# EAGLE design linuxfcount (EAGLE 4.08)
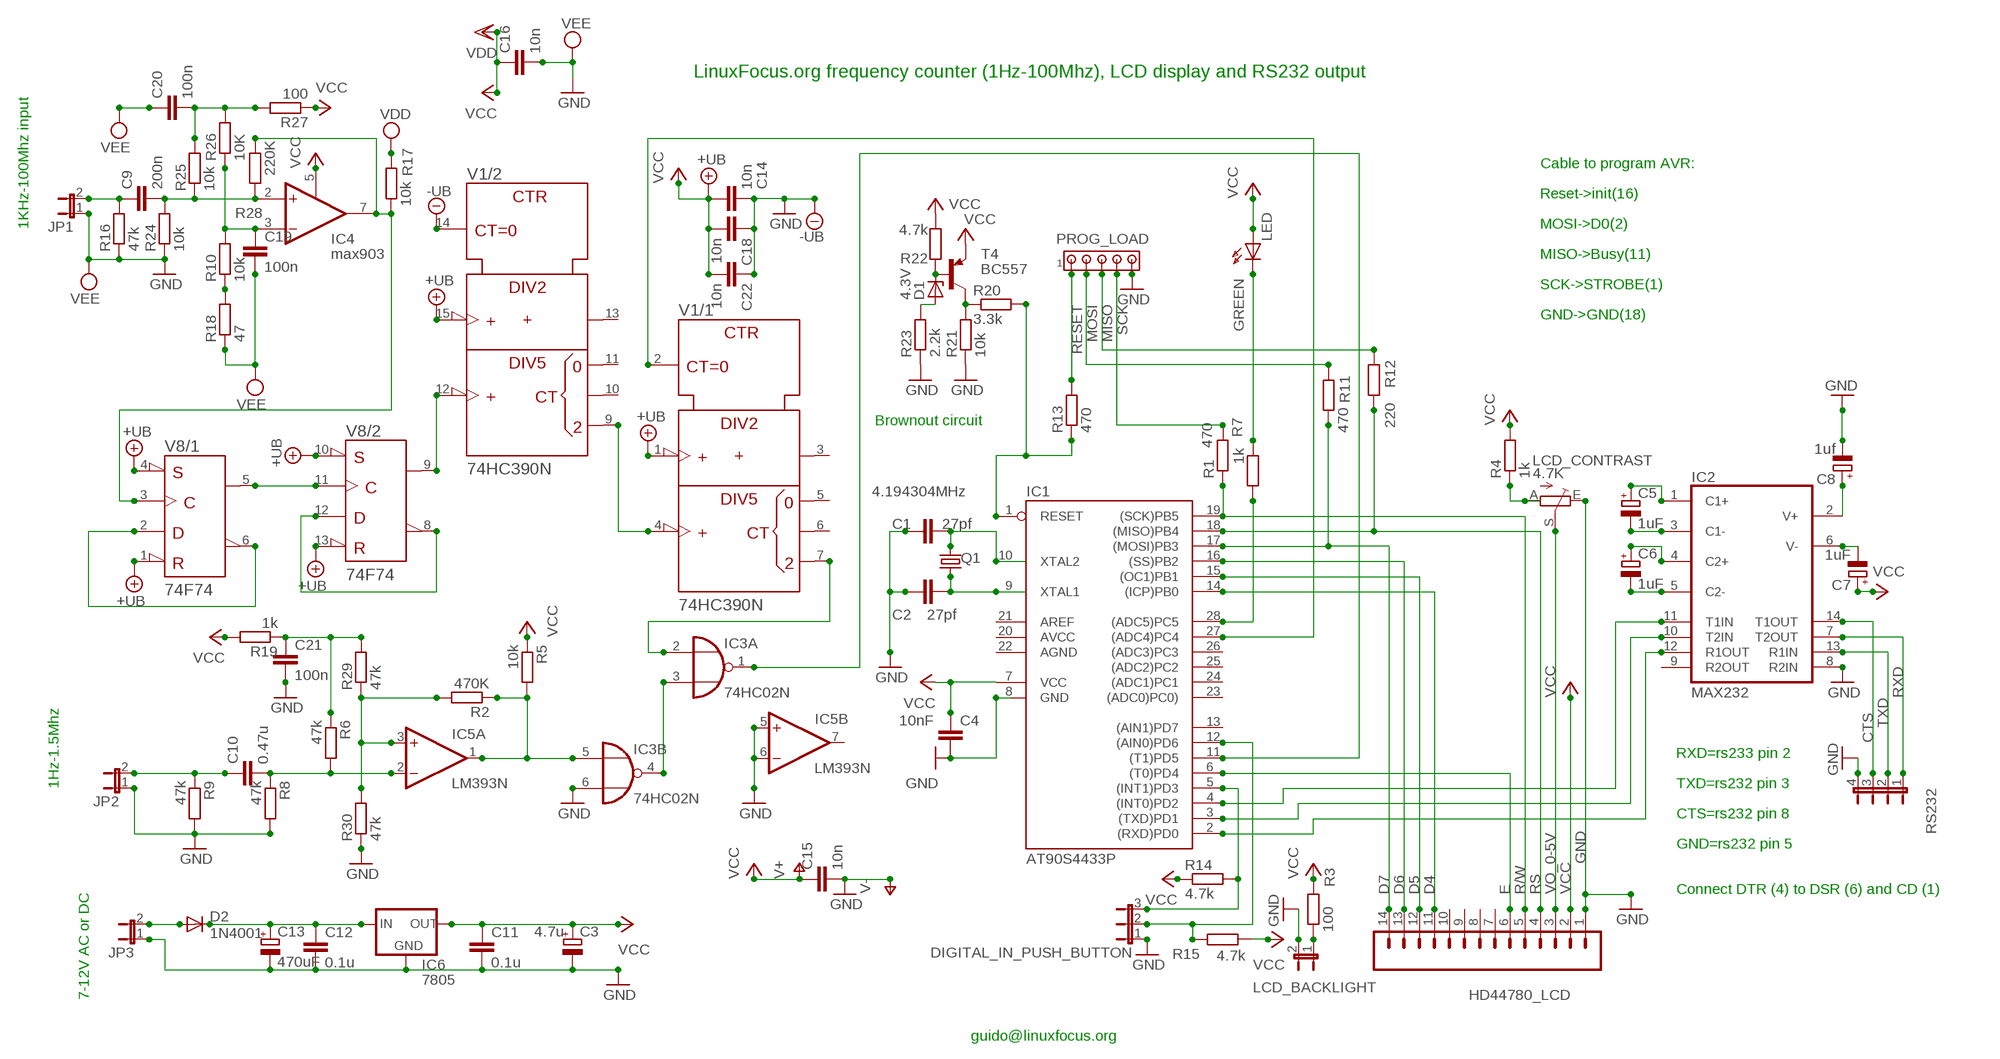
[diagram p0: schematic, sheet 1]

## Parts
C1  27pf  C2.5/2  [C2.5-2]
C2  27pf  C2.5/2  [C2.5-2]
C3  4.7u  CPOL-EUE2.5-7  [E2,5-7]
C4  10nF  C-EU025-030X050  [C025-030X050]
C5  1uF  CPOL-EUE2.5-6  [E2,5-6]
C6  1uF  CPOL-EUE2.5-6  [E2,5-6]
C7  1uF  CPOL-EUE2.5-6  [E2,5-6]
C8  1uf  CPOL-EUE2.5-6  [E2,5-6]
C9  200n  C-EU025-040X050  [C025-040X050]
C10  0.47u  C-EU025-040X050  [C025-040X050]
C11  0.1u  C-EU025-050X050  [C025-050X050]
C12  0.1u  C-EU025-050X050  [C025-050X050]
C13  470uF  CPOL-EUE5-10.5  [E5-10,5]
C14  10n  C-EU025-040X050  [C025-040X050]
C15  10n  C-EU025-040X050  [C025-040X050]
C16  10n  C-EU025-040X050  [C025-040X050]
C18  10n  C-EU025-040X050  [C025-040X050]
C19  100n  C-EU025-030X050  [C025-030X050]
C20  100n  C-EU025-030X050  [C025-030X050]
C21  100n  C-EU025-040X050  [C025-040X050]
C22  10n  C-EU025-030X050  [C025-030X050]
D1  4.3V  ZENER-DIODEZD-5  [ZDIO-5]
D2  1N4001  DIODE-DO07  [DO07]
DIGITAL_IN_PUSH_BUTTON  JP2E  [JP2]
GREEN  LED  LED3MM  [LED3MM]
HD44780_LCD  M14  [14P]
IC1  AT90S4433P  [DIL28-3]
IC2  MAX232  [DIL16]
IC3  74HC02N  [DIL14]
IC4  max903  MAX903CPA  [DIL08]
IC5  LM393N  [DIL08]
IC6  7805  78XXS  [78XXS]
JP1  JP1E  [JP1]
JP2  JP1E  [JP1]
JP3  JP1E  [JP1]
LCD_BACKLIGHT  JP1E  [JP1]
LCD_CONTRAST  4.7K  TRIM_EU-LI10  [LI10]
PROG_LOAD  MTA05-100  [10X05MTA]
Q1  4.194304MHz  HC49U-V  [HC49U-V]
R1  470  R-EU_0207/10  [0207/10]
R2  470K  R-EU_0204/5  [0204/5]
R3  100  R-EU_0204/5  [0204/5]
R4  1k  R-EU_0204/7  [0204/7]
R5  10k  R-EU_0204/7  [0204/7]
R6  47k  R-EU_0204/7  [0204/7]
R7  1k  R-EU_0204/7  [0204/7]
R8  47k  R-EU_0204/7  [0204/7]
R9  47k  R-EU_0204/7  [0204/7]
R10  10k  R-EU_0204/7  [0204/7]
R11  470  R-EU_0207/10  [0207/10]
R12  220  R-EU_0207/10  [0207/10]
R13  470  R-EU_0204/5  [0204/5]
R14  4.7k  R-EU_0207/10  [0207/10]
R15  4.7k  R-EU_0204/7  [0204/7]
R16  47k  R-EU_0204/7  [0204/7]
R17  10k  R-EU_0204/7  [0204/7]
R18  47  R-EU_0204/7  [0204/7]
R19  1k  R-EU_0204/7  [0204/7]
R20  3.3k  R-EU_0204/7  [0204/7]
R21  10k  R-EU_0204/7  [0204/7]
R22  4.7k  R-EU_0204/7  [0204/7]
R23  2.2k  R-EU_0204/7  [0204/7]
R24  10k  R-EU_0204/7  [0204/7]
R25  10k  R-EU_0204/5  [0204/5]
R26  10K  R-EU_0204/5  [0204/5]
R27  100  R-EU_0204/7  [0204/7]
R28  220K  R-EU_0204/5  [0204/5]
R29  47k  R-EU_0204/7  [0204/7]
R30  47k  R-EU_0204/5  [0204/5]
RS232  JP4E  [JP4]
T4  BC557  [TO92]
V1  74HC390N  74390N  [DIL16]
V8  74F74  7474N  [DIL14]

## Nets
+UB: V1.1(/1:CKA) V1.15(/2:CKA) V8.1(/1:CLR\) V8.4(/1:PRE\) V8.10(/2:PRE\) V8.13(/2:CLR\)
-UB: V1.14(/2:CLR)
CTS: IC2.14(T1OUT) RS232.3
D4: HD44780_LCD.11 IC1.14((ICP)PB0)
D5: HD44780_LCD.12 IC1.15((OC1)PB1)
D6: HD44780_LCD.13 IC1.16((SS)PB2)
D7: HD44780_LCD.14 IC1.17((MOSI)PB3) R11.1
E: HD44780_LCD.6 IC1.6((T0)PD4)
GND: C1.1 C2.1 C3.- C4.2 C8.- C11.2 C12.2 C13.- C14.2 C18.1 C21.2 C22.1 DIGITAL_IN_PUSH_BUTTON.1 HD44780_LCD.1 IC1.8(GND) IC2.8(R2IN) IC3.6(B:I1) IC5.5(B:+IN) IC5.6(B:-IN) IC6.GND JP1.1 JP2.1 JP3.1 LCD_BACKLIGHT.2 LCD_CONTRAST.E PROG_LOAD.5 R8.2 R9.2 R16.1 R21.1 R23.1 R24.1 R30.1 RS232.4 ; supply symbol labelled -UB, VEE
MISO: PROG_LOAD.3 R12.2
MOSI: PROG_LOAD.2 R11.2
N$1: IC3.3(A:I1) IC3.4(B:O)
N$2: C2.2 IC1.9(XTAL1) Q1.1
N$3: LCD_BACKLIGHT.1 R3.1
N$4: IC3.2(A:I0) V1.7(/1:QD)
N$5: IC1.28((ADC5)PC5) R7.2
N$6: DIGITAL_IN_PUSH_BUTTON.3 IC1.5((INT1)PD3) R14.2
N$7: GREEN.K(C) R7.1
N$8: V1.4(/1:CKB) V1.9(/2:QD)
N$9: V1.12(/2:CKB) V8.9(/2:Q)
N$10: C9.2 IC4.2(+IN) R24.2 R25.1 R28.1
N$11: C20.2 R25.2 R26.2 R27.2
N$12: V8.8(/2:Q\) V8.12(/2:D)
N$14: V8.5(/1:Q) V8.11(/2:CLK)
N$15: C19.1 IC4.3(-IN) R10.2 R26.1
N$16: R10.1 R18.2
N$17: C9.1 JP1.2 R16.2
N$18: C10.2 IC5.2(A:-IN) R6.2 R8.1
N$19: DIGITAL_IN_PUSH_BUTTON.2 IC1.12((AIN0)PD6) R15.2
N$20: C21.1 R6.1 R19.1 R29.2
N$21: IC5.3(A:+IN) R2.2 R29.1 R30.2
N$24: IC1.1(RESET) R13.1 R20.2
N$25: C6.- IC2.5(C2-)
N$26: C6.+ IC2.4(C2+)
N$27: C7.- IC2.6(V-)
N$28: C8.+ IC2.2(V+)
N$29: C5.- IC2.3(C1-)
N$30: C5.+ IC2.1(C1+)
N$31: IC1.3((TXD)PD1) IC2.10(T2IN)
N$32: IC1.4((INT0)PD2) IC2.11(T1IN)
N$34: IC1.2((RXD)PD0) IC2.12(R1OUT)
N$36: C1.2 IC1.10(XTAL2) Q1.2
N$37: IC4.7(OUT) R17.1 R28.2 V8.3(/1:CLK)
N$39: IC3.5(B:I0) IC5.1(A:OUT) R2.1 R5.2
N$40: IC1.11((T1)PD5) IC3.1(A:O)
N$42: C10.1 JP2.2 R9.1
N$45: LCD_CONTRAST.A R4.1
N$46: R20.1 R21.2 T4.3(C)
N$47: D1.A R23.2
N$48: D1.C R22.1 T4.2(B)
N$49: D2.A JP3.2
N$50: IC1.27((ADC4)PC4) V1.2(/1:CLR)
N$51: C12.1 C13.+ D2.C IC6.IN
N$52: V8.2(/1:D) V8.6(/1:Q\)
R/W: HD44780_LCD.5 IC1.19((SCK)PB5) R1.1
RESET: PROG_LOAD.1 R13.2
RS: HD44780_LCD.4 IC1.18((MISO)PB4) R12.1
RXD: IC2.7(T2OUT) RS232.1
SCK: PROG_LOAD.4 R1.2
TXD: IC2.13(R1IN) RS232.2
V+: C15.1 ; supply symbol labelled VCC
V-: C15.2 ; supply symbol labelled GND
VCC: C3.+ C4.1 C7.+ C11.1 C14.1 C16.1 C18.2 C22.2 GREEN.A HD44780_LCD.2 IC1.7(VCC) IC4.5(LATCH) IC6.OUT R3.2 R4.2 R5.1 R14.1 R15.1 R17.2 R19.2 R22.2 R27.1 T4.1(E) ; supply symbol labelled +UB, VDD
VEE: C16.2 C19.2 C20.1 R18.1 ; supply symbol labelled GND
VO_0-5V: HD44780_LCD.3 LCD_CONTRAST.S
Unconnected: HD44780_LCD.7 HD44780_LCD.8 HD44780_LCD.9 HD44780_LCD.10 IC1.13((AIN1)PD7) IC1.23((ADC0)PC0)) IC1.24((ADC1)PC1) IC1.25((ADC2)PC2) IC1.26((ADC3)PC3) IC2.9(R2OUT) IC3.8(C:I0) IC3.9(C:I1) IC3.10(C:O) IC3.11(D:I0) IC3.12(D:I1) IC3.13(D:O) IC5.7(B:OUT) V1.3(/1:QA) V1.5(/1:QB) V1.6(/1:QC) V1.10(/2:QC) V1.11(/2:QB) V1.13(/2:QA)

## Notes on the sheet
- LinuxFocus.org frequency counter (1Hz-100Mhz), LCD display and RS232 output
- Cable to program AVR:
- Reset->init(16)
- 1KHz-100Mhz input | MOSI->D0(2)
- MISO->Busy(11)
- SCK->STROBE(1)
- GND->GND(18)
- Brownout circuit
- RXD=rs233 pin 2
- 1Hz-1.5Mhz | TXD=rs232 pin 3
- CTS=rs232 pin 8
- GND=rs232 pin 5
- Connect DTR (4) to DSR (6) and CD (1)
- 7-12V AC or DC
- guido@linuxfocus.org

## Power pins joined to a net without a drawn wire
AGND: IC1.22(AGND)
AREF: IC1.21(AREF)
AVCC: IC1.20(AVCC)
GND: IC2.15(GND) IC3.7(P:GND) IC4.4(VEE) IC4.6(GND) V1.8(/-UB:-UB) V8.7(/-UB:-UB)
V+: IC5.8(P:V+)
V-: IC5.4(P:V-)
VCC: IC2.16(VCC) IC3.14(P:VCC) IC4.1(VCC) IC4.8(VDD) V1.16(/+UB:+UB) V8.14(/+UB:+UB)

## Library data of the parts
C1 C2 = capacitor-wima:C: CAPACITOR
C3 C5-C8 = rcl:CPOL-EU: POLARIZED CAPACITOR, European symbol
C4 = rcl:C-EU: CAPACITOR, European symbol
C9-C12 C14-C16 C18-C22 = rclgus:C-EU: CAPACITOR, European symbol
C13 = rclgus:CPOL-EU: POLARIZED CAPACITOR, European symbol
D1 = diode:ZENER-DIODE: Z-Diode
D2 = diode:DIODE-: DIODE
DIGITAL_IN_PUSH_BUTTON = jumper:JP2E: JUMPER
GREEN = led:LED3MM: LED
HD44780_LCD = con-amp-quick:M14: AMP QUICK CONNECTOR
IC1 = atmel:AT90S4433: MICROCONTROLLER 4 Kbytes FLASH 128 bytes SRAM 256 bytes EEPROM UART 6-channel 10 bit ADC
IC2 = maxim:MAX232: RS232 TRANSEIVER
IC3 = 74xx-eu:74*02: Quad 2-input NOR gate
IC4 = maxim2:MAX903CPA: VOLTAGE COMPARATOR
IC5 = linear:LM393: COMPARATOR
IC6 = v-reg:78XXS: VOLTAGE REGULATOR
JP1-JP3 LCD_BACKLIGHT = jumper:JP1E: JUMPER
LCD_CONTRAST = pot:TRIM_EU-: POTENTIOMETER
PROG_LOAD = con-amp:MTA05-100: AMP CONNECTOR
Q1 = crystal:HC49U-V: CRYSTAL
R1 R3 R7 R11-R14 R28 = rcl:R-EU_: RESISTOR, European symbol
R2 R5 R6 R8-R10 R16-R19 R24-R27 R29 R30 = rclgus:R-EU_: RESISTOR, European symbol
R4 R15 R20-R23 = rcl_gus:R-EU_: RESISTOR, European symbol
RS232 = jumper:JP4E: JUMPER
T4 = transistor-pnp:BC557: PNP TRANSISTOR
V1 = 74ttl-din:74*390: Dual 4-bit decade and binary COUNTER
V8 = 74ttl-din:74*74: Dual D type positive edge triggered FLIP FLOP, preset and clear

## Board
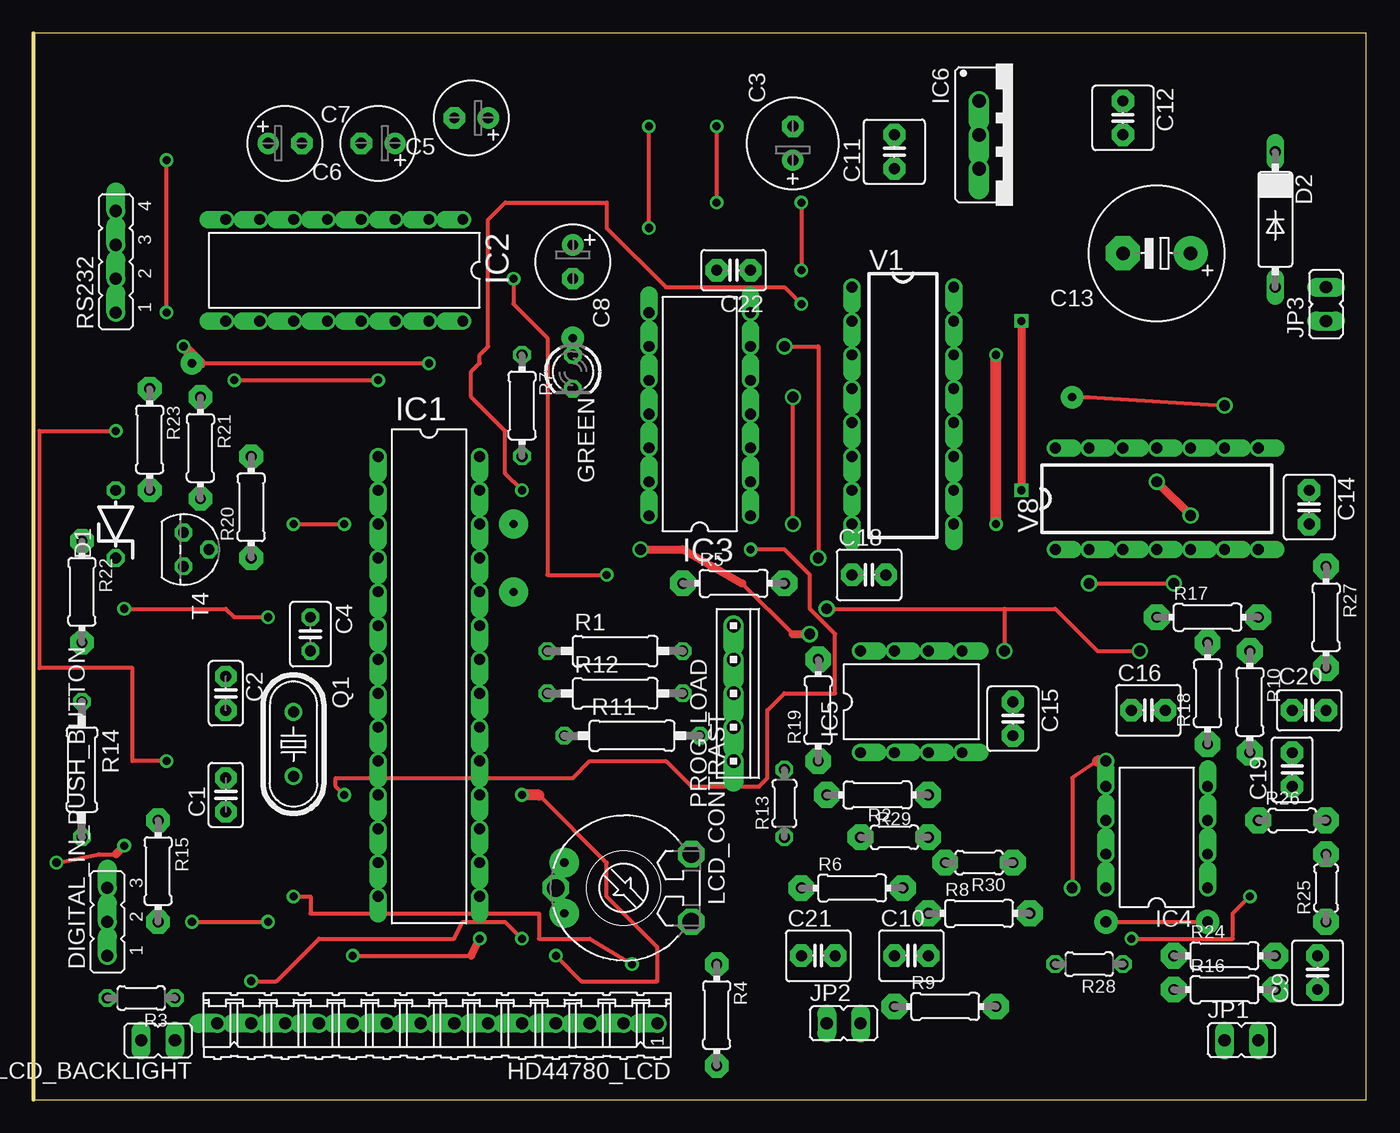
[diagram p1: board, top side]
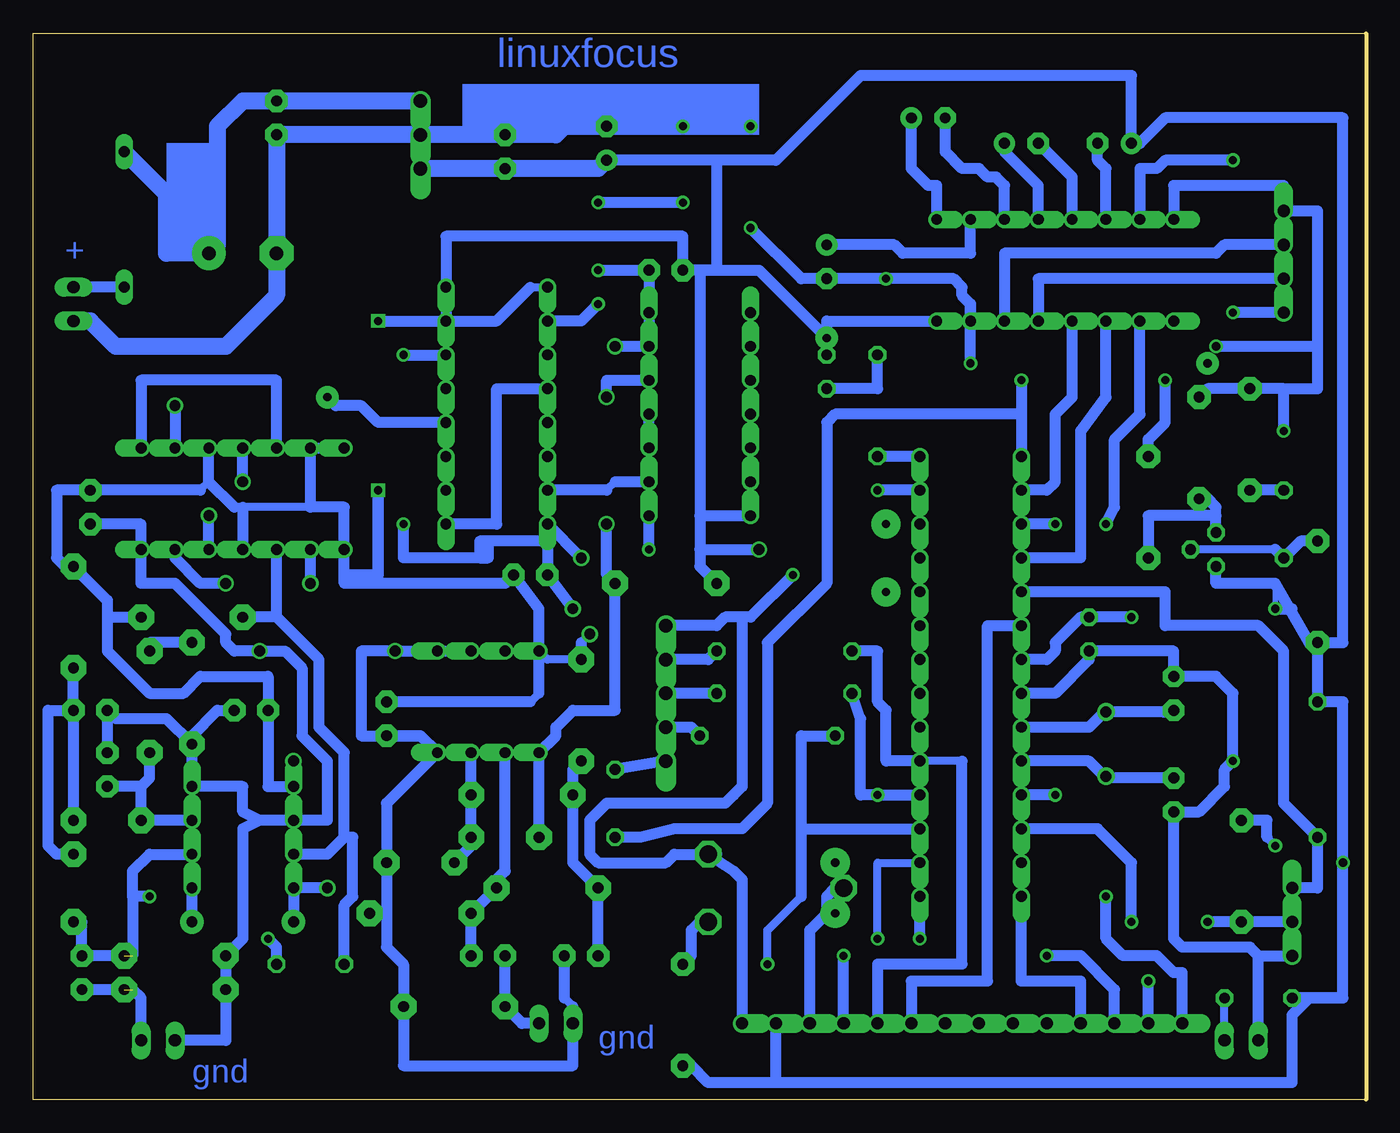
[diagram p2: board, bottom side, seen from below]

Size 100 x 80 mm. Coordinates in mm from the lower left corner, seen from the top.
Outline: 0,0 100,0 100,80 0,80 0,0
Copper layers used: Top, Bottom

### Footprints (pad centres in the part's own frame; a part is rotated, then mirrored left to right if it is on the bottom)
C2.5-2 = drill 0.813 pad 1.6 octagon: 1 -1.27,0; 2 1.27,0
E2,5-7 = drill 0.813 pad 1.6 round: + -1.27,0 | drill 0.813 pad 1.6 octagon: - 1.27,0
C025-030X050 = drill 0.813 octagon: 1 -1.27,0; 2 1.27,0
E2,5-6 = drill 0.813 pad 1.6 round: + -1.27,0 | drill 0.813 pad 1.6 octagon: - 1.27,0
C025-040X050 = drill 0.813 pad 1.676 octagon: 1 -1.27,0; 2 1.27,0
C025-050X050 = drill 0.813 pad 1.676 octagon: 1 -1.27,0; 2 1.27,0
E5-10,5 = drill 1.016 pad 2.54 round: + -2.54,0 | drill 1.016 pad 2.54 octagon: - 2.54,0
C025-030X050' = drill 0.813 pad 1.676 octagon: 1 -1.27,0; 2 1.27,0
ZDIO-5 = drill 0.813 octagon: A 2.54,0; C -2.54,0
DO07 = drill 0.813 long: A 5.08,0; C -5.08,0
JP2 = drill 0.914 offset: 1 -2.54,0; 2 0,0; 3 2.54,0
LED3MM = drill 0.813 octagon: A -1.27,0; K 1.27,0
14P = drill 0.914 offset: 1 -16.51,0; 2 -13.97,0; 3 -11.43,0; 4 -8.89,0; 5 -6.35,0; 6 -3.81,0; 7 -1.27,0; 8 1.27,0; 9 3.81,0; 10 6.35,0; 11 8.89,0; 12 11.43,0; 13 13.97,0; 14 16.51,0
DIL28-3 = drill 0.813 offset: 1 -16.51,-3.81; 2 -13.97,-3.81; 3 -11.43,-3.81; 4 -8.89,-3.81; 5 -6.35,-3.81; 6 -3.81,-3.81; 7 -1.27,-3.81; 8 1.27,-3.81; 9 3.81,-3.81; 10 6.35,-3.81; 11 8.89,-3.81; 12 11.43,-3.81; 13 13.97,-3.81; 14 16.51,-3.81; 15 16.51,3.81; 16 13.97,3.81; 17 11.43,3.81; 18 8.89,3.81; 19 6.35,3.81; 20 3.81,3.81; 21 1.27,3.81; 22 -1.27,3.81; 23 -3.81,3.81; 24 -6.35,3.81; 25 -8.89,3.81; 26 -11.43,3.81; 27 -13.97,3.81; 28 -16.51,3.81
DIL16 = drill 0.813 offset: 1 -8.89,-3.81; 2 -6.35,-3.81; 3 -3.81,-3.81; 4 -1.27,-3.81; 5 1.27,-3.81; 6 3.81,-3.81; 7 6.35,-3.81; 8 8.89,-3.81; 9 8.89,3.81; 10 6.35,3.81; 11 3.81,3.81; 12 1.27,3.81; 13 -1.27,3.81; 14 -3.81,3.81; 15 -6.35,3.81; 16 -8.89,3.81
DIL14 = drill 0.8 offset: 1 -7.62,-3.81; 2 -5.08,-3.81; 3 -2.54,-3.81; 4 0,-3.81; 5 2.54,-3.81; 6 5.08,-3.81; 7 7.62,-3.81; 8 7.62,3.81; 9 5.08,3.81; 10 2.54,3.81; 11 0,3.81; 12 -2.54,3.81; 13 -5.08,3.81; 14 -7.62,3.81
DIL08 = drill 0.813 offset: 1 -3.81,-3.81; 2 -1.27,-3.81; 3 1.27,-3.81; 4 3.81,-3.81; 5 3.81,3.81; 6 1.27,3.81; 7 -1.27,3.81; 8 -3.81,3.81
78XXS = drill 1.016 offset: GND 0,-2.54; IN -2.54,-2.54; OUT 2.54,-2.54
JP1 = drill 0.914 long: 1 0,-1.27; 2 0,1.27
LI10 = drill 1.321 octagon: A -2.54,-5.08; E 2.54,-5.08; S 0,5.08
10X05MTA = drill 1.016 offset: 1 5.08,0; 2 2.54,0; 3 0,0; 4 -2.54,0; 5 -5.08,0
HC49U-V = drill 0.813 round: 1 -2.413,0; 2 2.413,0
0207/10 = drill 0.813 octagon: 1 -5.08,0; 2 5.08,0
0204/5 = drill 0.813 pad 1.93 octagon: 1 -2.54,0; 2 2.54,0
0204/5' = drill 0.813 octagon: 1 -2.54,0; 2 2.54,0
0204/7 = drill 0.813 pad 1.778 octagon: 1 -3.81,0; 2 3.81,0
0204/7' = drill 0.813 pad 1.93 octagon: 1 -3.81,0; 2 3.81,0
0204/7'' = drill 0.813 octagon: 1 -3.81,0; 2 3.81,0
JP4 = drill 0.914 offset: 1 -3.81,0; 2 -1.27,0; 3 1.27,0; 4 3.81,0
TO92 = drill 0.813 octagon: 1 1.27,0; 2 0,1.905; 3 -1.27,0
DIL14' = drill 0.813 offset: 1 -7.62,-3.81; 2 -5.08,-3.81; 3 -2.54,-3.81; 4 0,-3.81; 5 2.54,-3.81; 6 5.08,-3.81; 7 7.62,-3.81; 8 7.62,3.81; 9 5.08,3.81; 10 2.54,3.81; 11 0,3.81; 12 -2.54,3.81; 13 -5.08,3.81; 14 -7.62,3.81

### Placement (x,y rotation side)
C1  14.44,22.86 90 top
C2  14.44,30.47 270 top
C3  56.98,71.75 90 top
C4  20.79,34.92 270 top
C5  32.85,73.66 180 top
C6  25.87,71.75 180 top
C7  18.88,71.75 0 top
C8  40.48,62.86 270 top
C9  96.36,9.52 90 top
C10  65.88,10.79 0 top
C11  64.61,71.11 90 top
C12  81.75,73.66 270 top
C13  84.29,63.5 180 top
C14  95.72,44.45 270 top
C15  73.5,28.57 270 top
C16  83.66,29.2 0 top
C18  62.7,39.37 0 top
C19  100n  [C025-030X050']  94.45,24.76 90 top
C20  100n  [C025-030X050']  95.72,29.2 0 top
C21  58.89,10.79 0 top
C22  10n  [C025-030X050']  52.54,62.23 180 top
D1  6.18,43.18 90 top
D2  93.18,66.03 270 top
DIGITAL_IN_PUSH_BUTTON  5.55,13.33 90 top
GREEN  40.48,54.61 270 top
HD44780_LCD  30.31,5.71 180 top
IC1  29.68,31.74 270 top
IC2  23.33,62.23 180 top
IC3  50,51.43 90 top
IC4  84.29,19.68 90 top
IC5  65.88,29.84 0 top
IC6  73.5,72.38 270 top
JP1  90.64,4.44 270 top
JP2  60.8,5.71 270 top
JP3  96.99,59.69 0 top
LCD_BACKLIGHT  9.36,4.44 90 top
LCD_CONTRAST  44.28,15.87 90 top
PROG_LOAD  52.54,30.47 270 top
Q1  19.52,26.66 270 top
R1  43.65,33.65 0 top
R2  64.61,19.68 0 top
R3  100  [0204/5']  8.09,7.62 180 top
R4  51.27,6.34 270 top
R5  10k  [0204/7']  52.54,38.73 0 top
R6  47k  [0204/7']  61.43,15.87 0 top
R7  1k  [0204/7'']  36.66,52.07 270 top
R8  47k  [0204/7']  70.95,13.97 0 top
R9  47k  [0204/7']  68.41,6.98 0 top
R10  10k  [0204/7']  91.28,29.84 270 top
R11  44.92,27.3 0 top
R12  43.65,30.47 0 top
R13  470  [0204/5']  56.35,22.22 90 top
R14  3.64,24.76 270 top
R15  9.36,17.14 270 top
R16  47k  [0204/7']  89.37,8.25 0 top
R17  10k  [0204/7']  88.1,36.19 0 top
R18  47  [0204/7']  88.1,30.47 90 top
R19  1k  [0204/7']  58.89,29.2 90 top
R20  16.34,44.45 90 top
R21  12.54,48.89 270 top
R22  3.64,38.1 270 top
R23  8.73,49.53 270 top
R24  10k  [0204/7']  89.37,10.79 0 top
R25  96.99,15.87 90 top
R26  94.45,20.95 0 top
R27  100  [0204/7']  96.99,36.19 270 top
R28  220K  [0204/5']  79.21,10.16 180 top
R29  47k  [0204/7']  63.34,22.86 180 top
R30  70.95,17.77 180 top
RS232  6.18,62.86 90 top
T4  11.27,41.27 270 top
V1  65.24,52.07 270 top
V8  74F74  [DIL14']  84.29,45.08 0 top

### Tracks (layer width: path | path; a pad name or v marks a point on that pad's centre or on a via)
+UB  (via drill 0.61)
  Top 0.305: v74.13,45.72 v74.13,58.41
  Bottom 0.61: 79.21,44.45 84.29,44.45 84.92,44.45 | 62.7,60.96 V1.1
  Bottom 0.813: 84.29,44.45 V8.4 | 84.92,44.45 86.83,46.35 V8.10 | 62.7,60.96 65.24,58.41 V1.15 v74.13,58.41 | 64.61,38.73 74.13,38.73 | 74.13,38.73 76.67,38.73 V8.1 76.67,44.45 79.21,44.45 V8.13 76.67,48.89 | 74.13,38.73 v74.13,45.72
CTS
  Bottom 0.813: IC2.14 27.14,63.5 11.27,63.5 10.63,64.13 RS232.3
D4
  Bottom 0.813: IC1.14 25.87,8.89 21.42,8.89 HD44780_LCD.11
D5  (via drill 0.61)
  Top 0.305: v23.96,10.79 32.85,10.79
  Top 0.61: 32.85,10.79 v33.49,12.06
  Bottom 0.813: HD44780_LCD.12 18.88,8.25 21.42,10.79 v23.96,10.79 | v33.49,12.06 IC1.15
D6  (via drill 0.61)
  Top 0.305: v16.34,8.89 18.25,8.89 21.42,12.06 31.58,12.06 32.22,13.33 35.39,13.33 v36.66,12.06
  Bottom 0.61: v36.66,12.06 36.66,17.77 IC1.16
  Bottom 0.813: HD44780_LCD.13 v16.34,8.89
D7  (via drill 0.61)
  Top 0.305: v19.52,15.24 20.79,15.24 20.79,13.97 37.94,13.97 37.94,12.06 41.74,12.06 v44.92,10.16
  Bottom 0.61: v44.92,10.16 44.92,12.7 42.38,15.24
  Bottom 0.813: R11.1 42.38,27.3 42.38,20.31 | 42.38,15.24 42.38,20.31 | HD44780_LCD.14 13.81,9.52 14.44,9.52 15.71,10.79 18.25,10.79 19.52,12.06 v19.52,15.24 | 42.38,20.31 IC1.17
E
  Bottom 0.813: HD44780_LCD.6 34.12,8.89 28.41,8.89 28.41,35.55 IC1.6
GND  (via drill 0.61, 0.81)
  Top 0.305: v83.02,33.65 79.84,33.65 76.67,36.83 72.86,36.83 | v59.52,36.83 72.86,36.83 | 72.86,36.83 v72.86,33.65 | v56.35,56.51 58.89,56.51 v58.89,40.64 | v72.22,43.18 v72.22,55.88 | v46.19,65.4 v46.19,73.02 | v57.62,67.3 v57.62,62.23 | v51.27,73.02 v51.27,67.3 | 12.54,55.24 v29.68,55.24 | v6.18,50.16 0.47,50.16 0.47,32.38 7.46,32.38 7.46,25.39 v10,25.39 | v43.02,39.37 38.57,39.37 38.57,57.15 36.03,59.69 v36.03,61.59
  Top 0.813: v72.22,43.18 v72.22,55.88 | v11.27,56.51 12.54,55.24
  Bottom 0.61: 59.52,6.98 60.16,7.62 | V1.8 61.43,41.91
  Bottom 0.813: IC4.4 84.29,23.49 84.29,21.58 83.02,20.95 | 83.02,20.95 IC4.6 77.94,20.95 77.94,25.39 79.84,27.3 79.84,32.38 81.11,33.65 v83.02,33.65 84.92,33.65 85.56,34.29 85.56,34.92 89.37,38.73 91.91,38.73 V8.7 91.91,43.18 C14.2 | 83.02,20.95 84.29,20.31 84.29,12.06 R24.1 R16.1 85.56,4.44 JP1.1 | 73.5,13.97 73.5,11.43 72.22,10.16 R9.2 72.22,2.54 59.52,2.54 JP2.1 59.52,6.98 | 73.5,13.97 R30.1 73.5,22.22 69.69,26.03 70.95,27.3 75.4,27.3 75.4,33.65 v72.86,33.65 IC5.5 IC5.6 | 73.5,13.97 R8.2 | 60.16,7.62 C21.2 | v59.52,36.83 C18.1 61.43,41.91 | v56.35,56.51 IC3.6 IC3.7 C22.1 v57.62,62.23 | v58.89,40.64 V1.8 | IC1.8 23.33,30.47 20.79,33.02 C4.2 14.44,33.65 C2.1 11.27,31.74 10,30.47 v10,25.39 10.63,24.76 10.63,23.49 12.54,21.58 C1.1 14.44,12.06 13.81,11.43 8.73,11.43 8.09,10.79 | 65.88,41.91 66.51,41.91 | 66.51,40.64 65.88,40.64 65.88,41.91 | 61.43,41.91 65.88,41.91 | v72.22,55.88 69.05,55.88 | v72.22,43.18 72.22,40.64 66.51,40.64 | 66.51,41.91 66.51,40.64 | 61.43,41.91 66.51,41.91 | 8.09,10.79 DIGITAL_IN_PUSH_BUTTON.1 | LCD_CONTRAST.E 48.73,18.41 | HD44780_LCD.1 46.82,16.5 47.46,17.14 LCD_CONTRAST.E | LCD_BACKLIGHT.2 8.09,10.79 | 11.9,53.34 R23.1 6.18,53.34 | IC2.8 14.44,68.57 6.18,68.57 RS232.4 3.64,66.67 3.64,56.51 | 3.64,56.51 3.64,53.34 6.18,53.34 | v46.19,65.4 42.38,61.59 C8.- v36.03,61.59 30.95,61.59 30.31,60.96 30.31,60.32 29.68,59.69 | C3.- v51.27,73.02 v46.19,73.02 | 29.68,59.69 IC2.15 | v51.27,67.3 v57.62,67.3 | v29.68,55.24 29.68,59.69 | 3.64,56.51 v11.27,56.51 | 11.9,53.34 R21.1 | 6.18,53.34 11.9,53.34 | v6.18,50.16 6.18,53.34 | PROG_LOAD.5 48.73,35.55 48.09,36.19 46.82,36.19 | 46.82,36.19 46.19,36.19 v43.02,39.37
  Bottom 0.813: LCD_CONTRAST.E 51.91,18.41 52.54,17.77 57.62,17.77 58.25,18.41 58.25,20.95 56.98,22.22 48.09,22.22 | 48.09,22.22 47.46,22.86 | 48.09,22.22 46.82,23.49 46.82,36.19
  Bottom 1.27: JP3.1 95.72,58.41 93.81,56.51 85.56,56.51 81.75,60.32 C13.- C12.2 IC6.GND C11.2 60.8,72.38 60.16,73.02 C3.-
MISO
  Bottom 0.813: R12.2 PROG_LOAD.3
MOSI
  Bottom 0.813: R11.2 50.63,27.93 PROG_LOAD.2
N$1
  Bottom 0.813: IC3.3 IC3.4
N$2
  Bottom 0.813: IC1.9 20.79,27.93 19.52,29.2 Q1.1 15.2,29.08 C2.2
N$3
  Bottom 0.61: LCD_BACKLIGHT.1 R3.1
N$4
  Bottom 0.61: 56.35,46.35 56.98,45.72
  Bottom 0.813: 56.98,45.72 V1.7 | IC3.2 56.35,46.35
N$5
  Bottom 0.813: IC1.28 R7.2
N$6
  Bottom 0.813: IC1.5 15.08,38.1 15.08,35.55 8.09,35.55 6.18,33.65 6.18,22.22 R14.2 3.64,15.87 DIGITAL_IN_PUSH_BUTTON.3
N$7
  Bottom 0.813: R7.1 36.66,53.34 GREEN.K
N$8
  Bottom 0.813: V1.4 65.24,53.34 65.24,43.18 V1.9
N$9  (via drill 0.61 pad 1.68, 0.81)
  Top 0.305: v77.94,52.7 79.21,52.7 v89.37,52.07
  Bottom 0.813: v89.37,52.07 V8.9 | V1.12 74.13,50.8 75.4,52.07 77.3,52.07 v77.94,52.7
N$10  (via drill 0.61)  (1 unrouted)
  Top 0.305: v82.39,12.06 90,12.06 90,13.97 v91.28,15.24
  Bottom 0.813: R25.1 96.36,13.33 C9.2 92.55,10.79 92.55,15.24 | 92.55,15.24 92.55,17.14 91.28,18.41 IC4.2 | R28.1 81.75,11.43 v82.39,12.06 | v91.28,15.24 92.55,15.24
N$11
  Bottom 0.813: C20.2 R26.2 | C20.2 R27.2 | R25.2 98.26,18.41 98.89,19.04 98.89,29.2 C20.2
N$12
  Bottom 0.813: V8.8 91.91,53.97 81.75,53.97 V8.12
N$13  (via drill 0.61 pad 2.18)
  other vias: 39.84,13.97
N$14  (via drill 0.81)
  Top 0.61: v86.83,43.81 v84.29,46.35
  Bottom 0.813: V8.5 v86.83,43.81 | v84.29,46.35 V8.11
N$15
  Bottom 0.813: IC4.3 R26.1 91.91,23.49 | 91.91,23.49 C19.1 | R10.2 91.28,24.12 91.91,23.49
N$16
  Bottom 0.813: R10.1 91.28,34.29 R18.2
N$17  (1 unrouted)
  Bottom 0.813: JP1.2 91.91,7.62 92.55,8.25 C9.1
N$18
  Bottom 0.813: C10.2 R8.1 R6.2 65.24,16.5 64.61,17.14 IC5.2
N$19  (via drill 0.61)
  Top 0.305: v11.9,13.33 v17.61,13.33
  Bottom 0.813: IC1.12 20.15,20.31 17.61,17.77 v17.61,13.33 | DIGITAL_IN_PUSH_BUTTON.2 R15.2 v11.9,13.33
N$20
  Bottom 0.61: 59.52,24.76 R19.1
  Bottom 0.813: C21.1 R6.1 59.52,17.77 R29.2 59.52,24.76
N$21
  Bottom 0.813: IC5.3 R29.1 R2.2 67.14,19.04 R30.2
N$22  (via drill 0.61 pad 2.18)
  other vias: 39.84,17.77
N$23  (via drill 0.61 pad 2.18)
  other vias: 36.03,43.18
N$24  (via drill 0.61)
  Top 0.305: v15.08,53.97 v25.87,53.97
  Bottom 0.813: R20.2 16.34,49.53 15.08,50.8 v15.08,53.97 | v25.87,53.97 25.87,51.43 | 25.87,51.43 IC1.1 | 25.87,51.43 39.84,51.43 40.48,50.8 40.48,38.73 44.92,34.29 44.92,22.22 46.82,20.31 51.91,20.31 54.45,19.68 R13.1
N$25
  Bottom 0.813: IC2.5 22.06,69.21 C6.-
N$26
  Bottom 0.813: C6.+ 27.14,71.11 24.6,68.57 IC2.4
N$27
  Bottom 0.813: C7.- 20.15,70.48 19.52,69.84 IC2.6
N$28
  Bottom 0.813: IC2.2 29.68,63.5 34.76,63.5 35.39,64.13 C8.+
N$29
  Bottom 0.813: C5.- 31.58,71.11 30.31,69.84 29.04,69.84 28.41,69.21 27.77,69.21 27.14,68.57 IC2.3
N$30
  Bottom 0.813: IC2.1 32.22,68.57 32.85,68.57 34.12,69.84 C5.+
N$31  (via drill 0.61)
  Top 0.305: v19.52,43.18 v23.33,43.18
  Bottom 0.813: IC2.10 16.98,51.43 18.88,49.53 18.88,44.45 v19.52,43.18 | v23.33,43.18 IC1.3
N$32
  Bottom 0.813: IC1.4 21.42,40.64 21.42,50.16 19.52,52.7 IC2.11
N$33  (via drill 0.61 pad 2.18)
  other vias: 36.03,38.1
N$34
  Bottom 0.813: IC2.12 22.06,52.7 23.33,51.43 23.33,46.35 23.96,45.72 IC1.2
N$35  (via drill 0.61 pad 1.68)
  other vias: 11.9,55.24
N$36
  Bottom 0.813: IC1.10 20.79,25.39 19.52,24.12 | 19.52,24.12 Q1.2 | C1.2 19.52,24.12
N$37
  Bottom 0.813: 81.75,36.19 V8.3 | 81.75,36.19 78.58,33.02 78.58,27.93 76.67,26.03 76.67,19.68 | 76.67,19.68 77.94,18.41 IC4.7 | 81.75,36.19 R17.1 | 76.67,19.68 76.03,19.68 76.03,15.24 76.67,14.6 R28.2
N$39  (via drill 0.81)
  Top 0.305: v56.98,43.18 v56.98,52.7
  Bottom 0.61: R2.1 IC5.1 | R5.2 56.98,39.37
  Bottom 0.813: R2.1 IC5.1 60.8,27.3 60.8,27.93 59.52,29.2 56.35,29.2 R5.2 | IC3.5 56.98,53.97 v56.98,52.7 | 56.98,39.37 v56.98,43.18
N$40  (via drill 0.61)
  Top 0.305: v53.81,41.27 56.35,41.27 58.25,39.37 58.25,36.83 60.16,34.92 60.16,30.47 56.35,30.47 55.08,29.2 55.08,24.12 54.45,23.49 49.37,23.49 47.46,25.39 41.74,25.39 40.48,24.12 22.7,24.12 22.7,23.49 v23.33,22.86
  Bottom 0.813: v53.81,41.27 IC3.1 | v23.33,22.86 IC1.11
N$42
  Bottom 0.813: JP2.2 63.34,5.71 R9.1 C10.1
N$45
  Bottom 0.813: LCD_CONTRAST.A 50,13.33 50.63,12.7 50.63,10.79 R4.1
N$46
  Bottom 0.813: R21.2 11.9,45.08 11.27,44.45 11.27,43.81 | T4.3 11.27,43.81 | 11.27,43.81 16.34,43.81 R20.1
N$47
  Bottom 0.813: D1.A R23.2
N$48
  Bottom 0.61: 6.82,41.27 T4.2
  Bottom 0.813: R22.1 4.92,41.91 D1.C 6.82,41.27
N$49
  Bottom 0.813: D2.A JP3.2
N$50  (via drill 0.61)
  Top 0.305: v36.66,45.72 35.39,46.98 35.39,50.16 32.85,52.7 32.85,54.61 33.49,55.24 33.49,55.88 34.12,56.51 34.12,66.03 35.39,67.3 43.02,67.3 43.02,65.4 47.46,60.96 56.35,60.96 v57.62,59.69
  Bottom 0.813: IC1.27 v36.66,45.72 | v57.62,59.69 58.89,58.41 V1.2
N$51
  Bottom 1.27: D2.C 90,67.94 90,63.5 C13.+ 86.19,64.13 86.19,73.02 84.29,74.92 C12.1 IC6.IN
N$52  (via drill 0.81)
  Top 0.305: v79.21,38.73 v85.56,38.73
  Bottom 0.813: V8.6 89.37,40.64 87.47,38.73 v85.56,38.73 | v79.21,38.73 V8.2
R/W
  Bottom 0.61: 30.31,25.39 IC1.19
  Bottom 0.813: R1.1 36.66,33.65 36.66,29.84 36.03,29.2 36.03,25.39 IC1.19 | 30.31,25.39 30.31,10.16 36.66,10.16 HD44780_LCD.5
RESET
  Bottom 0.813: PROG_LOAD.1 R13.2
RS  (via drill 0.61)
  Top 0.305: 37.94,22.86 43.02,17.77 43.02,15.24 46.82,11.43 46.82,8.89 41.11,8.89 v39.2,10.79
  Top 0.813: 37.94,22.86 v36.66,22.86
  Bottom 0.813: R12.1 37.94,28.57 37.94,22.86 v36.66,22.86 IC1.18 | HD44780_LCD.4 v39.2,10.79
RXD  (via drill 0.61)
  Top 0.305: v10,59.05 v10,70.48
  Bottom 0.813: IC2.7 16.98,69.84 15.71,69.84 15.08,70.48 v10,70.48 | RS232.1 v10,59.05
SCK
  Bottom 0.813: PROG_LOAD.4 49.37,33.02 R1.2
TXD
  Bottom 0.813: IC2.13 24.6,61.59 RS232.2
V+
  Bottom 0.61: 62.7,29.84 62.06,30.47
  Bottom 0.813: 62.06,30.47 IC5.8 | 62.7,29.84 C15.1
V-
  Bottom 0.813: C15.2 70.95,27.3 IC5.4
VCC  (via drill 0.61, 0.61 pad 1.68, 0.81, 0.81 pad 1.78)
  Top 0.305: v80.48,13.33 v88.1,13.33 | v77.94,15.87 77.94,24.12 79.84,25.39 | 53.17,38.73 56.98,34.92 | 6.18,18.41 4.92,18.41 v1.74,17.77 | v17.61,36.19 15.08,36.19 14.44,36.83 v6.82,36.83
  Top 0.61: 56.98,34.92 v58.25,34.92 | v45.55,41.27 48.73,41.27 53.17,38.73 | v74.13,58.41 v74.13,45.72 | 6.18,18.41 v6.82,19.04
  Top 0.813: v80.48,25.39 79.84,25.39
  Bottom 0.406: 6.82,38.73 v6.82,36.83
  Bottom 0.61: 87.47,45.72 86.83,46.35 84.92,44.45 79.21,44.45 | R19.2 61.43,33.02 62.06,33.65 | v58.25,34.92 58.89,34.29 | 69.05,58.41 v74.13,58.41 | 76.67,44.45 79.21,44.45 | 79.21,44.45 79.21,48.89 V8.14 | v6.82,19.04 7.46,19.68
  Bottom 0.813: v88.1,13.33 IC4.1 | v80.48,13.33 IC4.8 v77.94,15.87 | v80.48,25.39 IC4.5 82.39,23.49 C16.1 82.39,31.74 87.47,31.74 88.73,30.47 91.28,30.47 94.45,33.65 94.45,36.19 | 87.47,45.72 C14.1 98.26,45.72 98.26,40.64 97.62,40 R27.1 94.45,37.46 94.45,36.19 | 94.45,36.19 R17.2 | 69.05,58.41 V1.16 69.05,64.77 51.27,64.77 C22.2 50,62.23 | 62.06,33.65 62.06,36.83 C18.2 | 50,62.23 50,43.81 | 50,43.81 50,41.27 | R5.1 50,40 50,41.27 | 58.89,34.29 R19.2 | 50,41.27 v45.55,41.27 | IC1.7 23.96,33.02 23.33,33.65 23.33,34.29 21.42,36.19 C4.1 v17.61,36.19 | R4.2 50.63,2.54 49.37,1.27 44.28,1.27 | v74.13,45.72 74.13,39.37 76.67,39.37 76.67,44.45 | R15.1 7.46,20.95 7.46,19.68 | R22.2 R14.1 1.74,29.84 v1.74,17.77 1.74,7.62 | R22.2 1.74,34.29 1.74,73.66 15.08,73.66 16.98,71.75 C7.+ 17.61,76.83 37.94,76.83 44.28,70.48 48.73,70.48 | 48.73,70.48 C3.+ | 1.74,7.62 4.28,7.62 5.55,6.34 5.55,1.27 44.28,1.27 | 1.74,7.62 R3.2 | 44.28,1.27 HD44780_LCD.2 | R22.2 4.28,34.29 6.82,38.73 11.27,38.73 T4.1 | 50,62.23 48.73,62.23 48.73,70.48 | 50,62.23 45.55,62.23 v40.48,57.15 | v40.48,57.15 GREEN.A | v6.82,36.83 5.55,36.83 | v40.48,57.15 40.48,58.41 IC2.16 | 50,43.81 IC3.14
  Bottom 1.27: IC6.OUT C11.1 57.62,69.84 C3.+
VEE
  Bottom 0.813: C19.2 C20.1 93.81,28.57 90,28.57 R18.1 | 88.1,23.49 R18.1 | C16.2 86.19,29.2 88.1,27.3 R18.1
VO_0-5V
  Bottom 0.813: LCD_CONTRAST.S 39.84,15.87 40.48,15.24 40.48,13.97 41.74,12.7 HD44780_LCD.3
(copper drawn outside any net)
  shapes: Bottom area x2

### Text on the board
Bottom: linuxfocus | + | gnd | gnd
